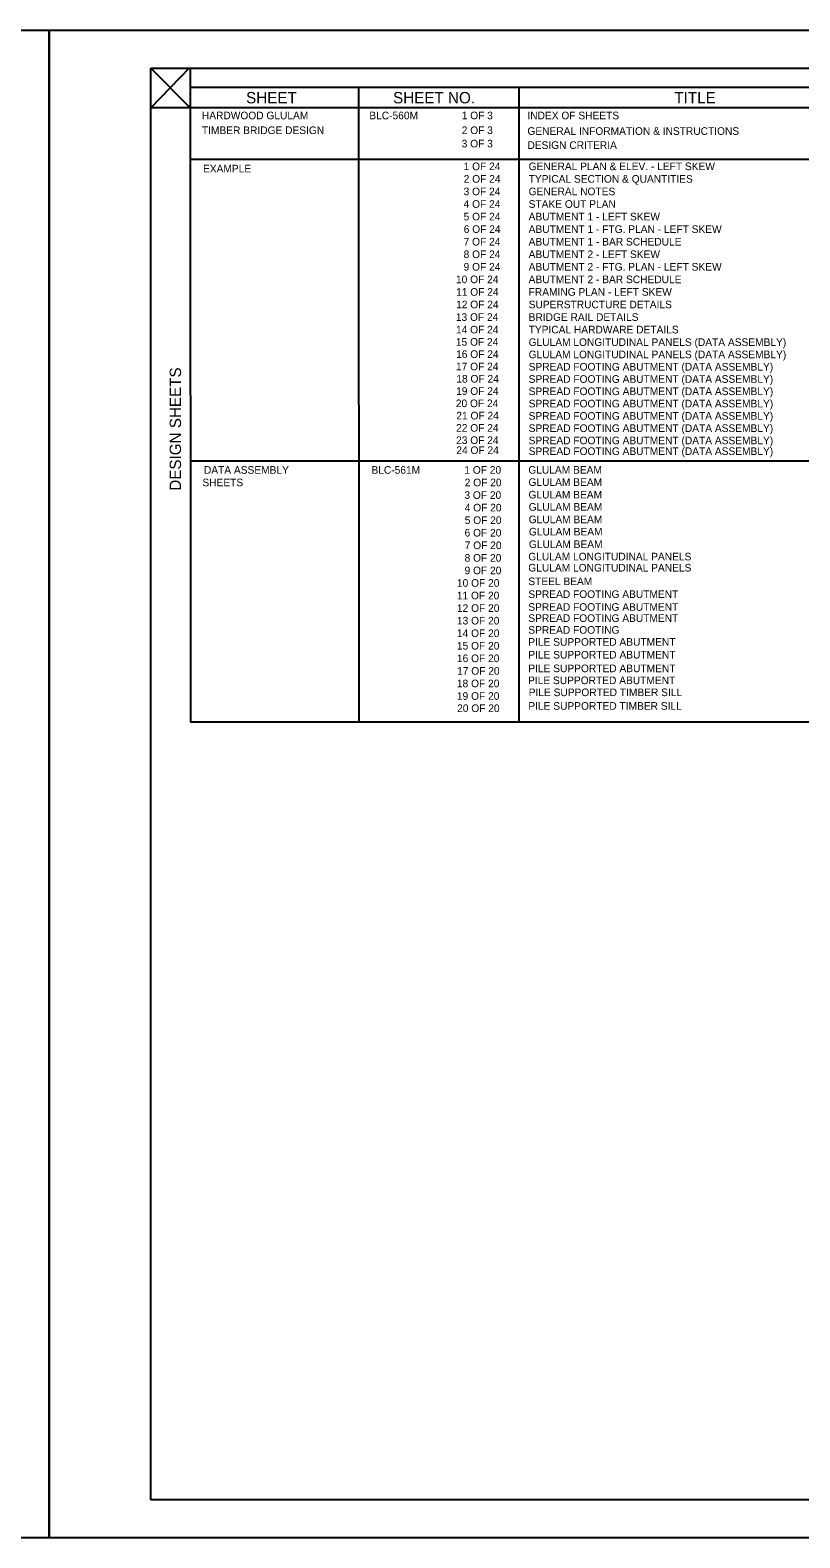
# Model space of a CAD drawing. Extents: x 637594 to 640253, y 297247 to 298435.
# Drawn here: x 638428 to 638731, y 297247 to 297841 of the extents above; entities that cross this region are included whole.
import ezdxf

# ---------------------------------------------------------------- set-up
doc = ezdxf.new("R2010")
doc.units = 0
for name, color, linetype in [('2', 7, 'Continuous'), ('4', 7, 'Continuous'), ('6', 7, 'Continuous'), ('PLT-BNDY', 7, 'Continuous')]:
    doc.layers.add(name, color=color, linetype=linetype)

msp = doc.modelspace()

# ---------------------------------------------------------------- linework, layer by layer
at = {"layer": '2'}
for p, q in [((638475.46, 297262.46), (638475.46, 297826.46)), ((638475.46, 297826.46), (639261.46, 297826.46)), ((639261.46, 297262.46), (638475.46, 297262.46))]:
    msp.add_line(p, q, dxfattribs=at)
at = {"layer": '4'}
for p, q in [((638475.46, 297826.46), (638491.02, 297810.83)), ((638490.54, 297826.46), (638475.46, 297810.83)), ((638491.02, 297826.46), (638491.06, 297568.84)), ((638557.3, 297818.89), (638557.34, 297568.84)), ((638620.35, 297818.89), (638620.39, 297568.84)), ((638788.71, 297810.83), (638475.46, 297810.83)), ((638762.01, 297790.44), (638491.02, 297790.44)), ((638762.04, 297671.68), (638491.1, 297671.68)), ((638762.05, 297568.84), (638491.06, 297568.84))]:
    msp.add_line(p, q, dxfattribs=at)
at = {"layer": '6'}
msp.add_line((639044.75, 297818.89), (638491.02, 297818.89), dxfattribs=at)
at = {"layer": 'PLT-BNDY'}
for points in [[(637594.46, 297841.46), (638435.46, 297841.46), (638435.46, 297247.46), (637594.46, 297247.46)], [(638435.46, 297841.46), (639276.46, 297841.46), (639276.46, 297247.46), (638435.46, 297247.46)]]:
    msp.add_lwpolyline(points, close=True, dxfattribs=at)

# ---------------------------------------------------------------- texts
at = {"layer": '2'}
for s, height, p in [('SHEET', 4.479, (638512.98, 297812.62)), ('SHEET NO.', 4.479, (638570.85, 297812.62)), ('TITLE', 4.479, (638681.62, 297812.62)), ('HARDWOOD GLULAM', 3.0001, (638495.58, 297806.34)), ('BLC-560M', 3, (638561.51, 297806.34)), ('1 OF 3', 3, (638597.89, 297806.34)), ('INDEX OF SHEETS', 3.0001, (638623.76, 297806.34)), ('TIMBER BRIDGE DESIGN', 3.0001, (638495.58, 297800.52)), ('2 OF 3', 3, (638597.89, 297800.52)), ('GENERAL INFORMATION & INSTRUCTIONS', 3.0001, (638623.76, 297800.21)), ('3 OF 3', 3, (638597.89, 297795.26)), ('DESIGN CRITERIA', 3.0001, (638623.76, 297794.66)), ('EXAMPLE', 3, (638496.01, 297785.4)), ('2 OF 24', 3, (638598.67, 297781.36)), ('1 OF 24', 3, (638598.63, 297786.3)), ('TYPICAL SECTION & QUANTITIES', 3.0001, (638624.24, 297781.36)), ('GENERAL PLAN & ELEV. - LEFT SKEW', 3.0001, (638624.24, 297786.3)), ('3 OF 24', 3, (638598.63, 297776.41)), ('GENERAL NOTES', 3.0001, (638624.24, 297776.41)), ('4 OF 24', 3, (638598.63, 297771.46)), ('STAKE OUT PLAN', 3.0001, (638624.24, 297771.46)), ('5 OF 24', 3, (638598.63, 297766.51)), ('ABUTMENT 1 - LEFT SKEW', 3.0001, (638624.24, 297766.51)), ('6 OF 24', 3, (638598.67, 297761.56)), ('ABUTMENT 1 - FTG. PLAN - LEFT SKEW', 3.0001, (638624.24, 297761.56)), ('8 OF 24', 3, (638598.63, 297751.66)), ('7 OF 24', 3, (638598.63, 297756.61)), ('ABUTMENT 1 - BAR SCHEDULE', 3.0001, (638624.24, 297756.61)), ('ABUTMENT 2 - LEFT SKEW', 3.0001, (638624.24, 297751.66)), ('9 OF 24', 3, (638598.63, 297746.72)), ('ABUTMENT 2 - FTG. PLAN - LEFT SKEW', 3.0001, (638624.24, 297746.72)), ('10 OF 24', 3, (638595.63, 297741.77)), ('ABUTMENT 2 - BAR SCHEDULE', 3.0001, (638624.24, 297741.77)), ('11 OF 24', 3, (638595.67, 297736.82)), ('FRAMING PLAN - LEFT SKEW', 3.0001, (638624.24, 297736.82)), ('12 OF 24', 3, (638595.67, 297731.87)), ('SUPERSTRUCTURE DETAILS', 3.0001, (638624.24, 297731.87)), ('13 OF 24', 3, (638595.58, 297726.92)), ('14 OF 24', 3, (638595.63, 297721.98)), ('TYPICAL HARDWARE DETAILS', 3.0001, (638624.24, 297721.98)), ('BRIDGE RAIL DETAILS', 3.0001, (638624.24, 297726.92)), ('15 OF 24', 3, (638595.58, 297717.14)), ('GLULAM LONGITUDINAL PANELS (DATA ASSEMBLY)', 3.0001, (638624.24, 297717.03)), ('16 OF 24', 3, (638595.67, 297712.3)), ('GLULAM LONGITUDINAL PANELS (DATA ASSEMBLY)', 3.0001, (638624.24, 297712.19)), ('17 OF 24', 3, (638595.63, 297707.45)), ('SPREAD FOOTING ABUTMENT (DATA ASSEMBLY)', 3.0001, (638624.24, 297707.35)), ('18 OF 24', 3, (638595.77, 297702.61)), ('SPREAD FOOTING ABUTMENT (DATA ASSEMBLY)', 3.0001, (638624.24, 297702.51)), ('20 OF 24', 3, (638595.58, 297692.93)), ('19 OF 24', 3, (638595.68, 297697.77)), ('SPREAD FOOTING ABUTMENT (DATA ASSEMBLY)', 3.0001, (638624.24, 297697.67)), ('SPREAD FOOTING ABUTMENT (DATA ASSEMBLY)', 3.0001, (638624.24, 297692.83)), ('21 OF 24', 3, (638595.77, 297688.09)), ('SPREAD FOOTING ABUTMENT (DATA ASSEMBLY)', 3.0001, (638624.24, 297687.98)), ('22 OF 24', 3, (638595.68, 297683.25)), ('SPREAD FOOTING ABUTMENT (DATA ASSEMBLY)', 3.0001, (638624.24, 297683.14)), ('23 OF 24', 3, (638595.68, 297678.41)), ('24 OF 24', 3, (638595.77, 297674.47)), ('SPREAD FOOTING ABUTMENT (DATA ASSEMBLY)', 3.0001, (638624.24, 297678.3)), ('SPREAD FOOTING ABUTMENT (DATA ASSEMBLY)', 3.0001, (638624.24, 297674.08)), ('DATA ASSEMBLY', 3.0001, (638496.39, 297666.69)), ('BLC-561M', 3, (638562.33, 297666.69)), ('1 OF 20', 3, (638598.91, 297666.69)), ('GLULAM BEAM', 3.0001, (638624.11, 297666.72)), ('SHEETS', 3, (638495.78, 297661.74)), ('3 OF 20', 3, (638598.94, 297656.79)), ('2 OF 20', 3, (638599.07, 297661.74)), ('GLULAM BEAM', 3.0001, (638624.19, 297661.9)), ('GLULAM BEAM', 3.0001, (638624.19, 297656.95)), ('4 OF 20', 3, (638599.07, 297651.85)), ('GLULAM BEAM', 3.0001, (638624.27, 297652.14)), ('5 OF 20', 3, (638599.07, 297646.9)), ('GLULAM BEAM', 3.0001, (638624.27, 297647.19)), ('6 OF 20', 3, (638599.01, 297641.95)), ('GLULAM BEAM', 3.0001, (638624.35, 297642.37)), ('7 OF 20', 3, (638599.07, 297637)), ('GLULAM LONGITUDINAL PANELS', 3.0001, (638624.11, 297632.56)), ('GLULAM BEAM', 3.0001, (638624.35, 297637.43)), ('8 OF 20', 3, (638599.01, 297632.05)), ('9 OF 20', 3, (638599.01, 297627.1)), ('GLULAM LONGITUDINAL PANELS', 3.0001, (638624.11, 297628.17)), ('10 OF 20', 3, (638596, 297622.16)), ('STEEL BEAM', 3, (638624.11, 297622.8)), ('11 OF 20', 3, (638595.97, 297617.21)), ('SPREAD FOOTING ABUTMENT', 3.0001, (638624.11, 297617.75)), ('12 OF 20', 3, (638596, 297612.26)), ('SPREAD FOOTING ABUTMENT', 3.0001, (638624.11, 297612.7)), ('13 OF 20', 3, (638596, 297607.31)), ('SPREAD FOOTING ABUTMENT', 3.0001, (638624.11, 297608.31)), ('SPREAD FOOTING', 3.0001, (638624.11, 297603.66)), ('14 OF 20', 3, (638596, 297602.36)), ('15 OF 20', 3, (638596, 297597.42)), ('PILE SUPPORTED ABUTMENT', 3.0001, (638624.11, 297598.93)), ('16 OF 20', 3, (638596, 297592.47)), ('PILE SUPPORTED ABUTMENT', 3.0001, (638624.11, 297593.88)), ('17 OF 20', 3, (638596.07, 297587.52)), ('PILE SUPPORTED ABUTMENT', 3.0001, (638624.11, 297588.51)), ('18 OF 20', 3, (638596, 297582.57)), ('PILE SUPPORTED ABUTMENT', 3.0001, (638624.01, 297583.8)), ('PILE SUPPORTED TIMBER SILL', 3.0001, (638624.26, 297579.08)), ('19 OF 20', 3, (638596, 297577.62)), ('PILE SUPPORTED TIMBER SILL', 3.0001, (638624.13, 297573.71)), ('20 OF 20', 3, (638596.08, 297572.81))]:
    msp.add_text(s, height=height, dxfattribs=at).set_placement(p)
msp.add_text('DESIGN SHEETS', height=4.4794, rotation=90, dxfattribs=at).set_placement((638487.36, 297660))

doc.saveas('drawing.dxf')
